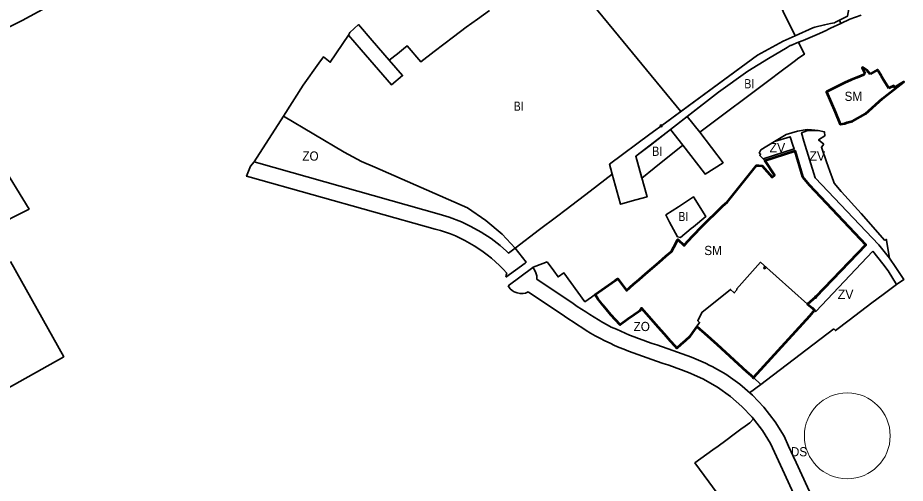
# Model space of a CAD drawing. Extents: x -650276 to -642489, y -1074311 to -1066720.
# Drawn here: x -648741 to -647583, y -1071705 to -1071099 of the extents above; entities that cross this region are included whole.
import ezdxf

# ---------------------------------------------------------------- set-up
doc = ezdxf.new("R2010")
doc.units = 0
doc.header["$LTSCALE"] = 4.8
doc.header["$PDMODE"] = 32
doc.header["$PDSIZE"] = 2.4
for name, color, linetype, lineweight in [('1', 7, 'Continuous', 35), ('15', 7, 'Continuous', 35), ('18', 7, 'Continuous', 35), ('2', 7, 'Continuous', 35), ('24', 7, 'Continuous', 35), ('40', 7, 'Continuous', 35), ('42', 7, 'Continuous', 35), ('54', 7, 'Continuous', 35), ('60', 7, 'Continuous', 53), ('7', 7, 'Continuous', 35)]:
    doc.layers.add(name, color=color, linetype=linetype, lineweight=lineweight)
doc.layers.add('62', color=7, linetype='Continuous')

msp = doc.modelspace()

# ---------------------------------------------------------------- linework, layer by layer
at = {"layer": '1'}
msp.add_lwpolyline([(-648001.922, -1071067.83), (-647977.41, -1071049.74), (-647930.7, -1071017.18), (-647911.838, -1071002.919), (-647864.03, -1070969.3), (-647864.03, -1070969.3), (-647818.33, -1070942.91), (-647810.243, -1070939.825), (-647759.52, -1071055.67), (-647757.19, -1071059.66), (-647742.64, -1071090.72), (-647726.74, -1071122.48), (-647742.35, -1071129.43), (-647775.982, -1071148.001), (-647775.982, -1071148.001), (-647875.939, -1071221.104)], close=True, dxfattribs=at)
at = {"layer": '15'}
for p, q in [((-647873.25, -1071265.17), (-647845.18, -1071301.54)), ((-647708.429, -1071316.821), (-647717.363, -1071306.29))]:
    msp.add_line(p, q, dxfattribs=at)
for points in [[(-647676.96, -1071039.014), (-647676.9, -1071039.03), (-647676.45, -1071039.22), (-647656.443, -1071085.369), (-647658.55, -1071097.02), (-647669.02, -1071102.33), (-647667.35, -1071106.38), (-647655.47, -1071100.98), (-647640.727, -1071095.819)], [(-647845.18, -1071301.54), (-647844.296, -1071302.757), (-647820.698, -1071287.83), (-647850.956, -1071248.208), (-647867.586, -1071227.694), (-647889.22, -1071244.48), (-647873.25, -1071265.17)]]:
    msp.add_lwpolyline(points, dxfattribs=at)
for points in [[(-648238.84, -1071174.33), (-648256.04, -1071154.5), (-648278.39, -1071128.74), (-648296.34, -1071108.04), (-648307.33, -1071118.47), (-648309.41, -1071121.655), (-648292.587, -1071141.054), (-648270.236, -1071166.815), (-648253.126, -1071186.542)], [(-647826.56, -1071195.86), (-647788.66, -1071168.8), (-647761.366, -1071152.304), (-647737.027, -1071137.593), (-647733.38, -1071135.37), (-647732.58, -1071135.04), (-647722.51, -1071130.93), (-647716.51, -1071128.48), (-647695.08, -1071119.72), (-647685.55, -1071115.14), (-647684.15, -1071114.47), (-647680.64, -1071112.77), (-647667.35, -1071106.38), (-647669.02, -1071102.33), (-647674.17, -1071104.97), (-647675.64, -1071105.71), (-647680.82, -1071106.54), (-647688.45, -1071108.38), (-647701.04, -1071111.41), (-647703.96, -1071112.11), (-647726.74, -1071122.48), (-647742.35, -1071129.43), (-647775.982, -1071148.001), (-647895.959, -1071235.746), (-647916.161, -1071250.628), (-647916.208, -1071250.662), (-647968.896, -1071289.779), (-647965.26, -1071302.86), (-647954.38, -1071342), (-647934.51, -1071336.37), (-647919.88, -1071332.23), (-647924.53, -1071315.55), (-647934.6, -1071279.45), (-647915.6, -1071264.95), (-647889.22, -1071244.48)], [(-647625.428, -1071403.267), (-647612.269, -1071419.742), (-647605.292, -1071428.816), (-647594.43, -1071446.543), (-647585.273, -1071440.044), (-647595.335, -1071424.564), (-647603.9, -1071412.1), (-647617.49, -1071394.901), (-647700.816, -1071307.512), (-647715.355, -1071259.885), (-647718.342, -1071248.972), (-647711.447, -1071246.332), (-647696.81, -1071245.79), (-647705.59, -1071245.08), (-647710.94, -1071244.65), (-647723.57, -1071246.66), (-647738.56, -1071251.13), (-647753.647, -1071260.178), (-647733.15, -1071254.081), (-647729.795, -1071265.066), (-647728.006, -1071269.975), (-647768.445, -1071282.6), (-647772.97, -1071278.43), (-647772.07, -1071279.33), (-647766.35, -1071285.11), (-647727.368, -1071272.362), (-647717.363, -1071306.29), (-647708.429, -1071316.821), (-647634.524, -1071394.901), (-647700.078, -1071462.96), (-647710.546, -1071472.023), (-647699.767, -1071481.617)]]:
    msp.add_lwpolyline(points, close=True, dxfattribs=at)
for p in [(-647766.557, -1071424.793), (-647700.078, -1071462.96)]:
    msp.add_point(p, dxfattribs=at)
at = {"layer": '18'}
for points in [[(-647629.09, -1071172.4), (-647632.93, -1071167.71), (-647638.46, -1071163.89), (-647639.32, -1071164.22), (-647635.93, -1071171.22)], [(-647612.695, -1071177.542), (-647613.91, -1071175.57), (-647614.732, -1071174.222), (-647618.446, -1071168.166), (-647618.469, -1071168.129), (-647618.77, -1071167.64), (-647619.264, -1071166.832), (-647619.34, -1071166.709), (-647628.39, -1071172.05), (-647629.09, -1071172.4)], [(-647635.93, -1071171.22), (-647637.87, -1071173.29), (-647646.09, -1071176.68), (-647653.85, -1071179.87), (-647662.634, -1071183.968)], [(-647604.576, -1071190.781), (-647604.888, -1071190.272), (-647612.695, -1071177.542)], [(-647662.634, -1071183.968), (-647686.01, -1071195.35), (-647686.01, -1071195.35)], [(-647674.6, -1071221.71), (-647668.226, -1071237.571), (-647667.77, -1071237.5), (-647661.99, -1071236.62), (-647658.78, -1071235.63), (-647651.93, -1071233.57), (-647635.17, -1071224.18), (-647613.09, -1071204.33), (-647607.02, -1071199.34), (-647584.92, -1071182.54), (-647597.164, -1071189.857), (-647598.215, -1071187.608), (-647604.576, -1071190.781)], [(-647686.01, -1071195.35), (-647686.01, -1071195.35), (-647674.6, -1071221.71)]]:
    msp.add_lwpolyline(points, dxfattribs=at)
msp.add_lwpolyline([(-647974.66, -1071450.62), (-647977.28, -1071452.43), (-647979.88, -1071454.22), (-647982.46, -1071456), (-647985.06, -1071457.79), (-647987.8, -1071459.68), (-647984.07, -1071465.1), (-647977.13, -1071474.05), (-647972.76, -1071479), (-647967.13, -1071486.01), (-647957.07, -1071497.13), (-647955.14, -1071499.23), (-647950.56, -1071495.85), (-647944.81, -1071491.78), (-647939.31, -1071487.88), (-647933.88, -1071484.04), (-647931.17, -1071482.12), (-647929.26, -1071480.77), (-647927.2, -1071477.54), (-647919.22, -1071486.5), (-647881.16, -1071529.25), (-647876.27, -1071524.96), (-647864.69, -1071514.65), (-647851.45, -1071495.96), (-647853.77, -1071493.78), (-647848.4, -1071482.78), (-647810.97, -1071452.92), (-647806.15, -1071457.48), (-647802.53, -1071453.19), (-647803.1, -1071452.66), (-647771.82, -1071417.42), (-647710.546, -1071472.023), (-647700.078, -1071462.96), (-647634.524, -1071394.901), (-647708.429, -1071316.821), (-647717.363, -1071306.29), (-647727.368, -1071272.362), (-647766.35, -1071285.11), (-647753.89, -1071303.94), (-647756.67, -1071306.77), (-647769.85, -1071291.91), (-647774.14, -1071291.34), (-647777.4, -1071291.32), (-647815.95, -1071339.71), (-647820.93, -1071344.25), (-647849.86, -1071372.18), (-647867.45, -1071390.95), (-647871.68, -1071395.59), (-647879.76, -1071387.96), (-647885.05, -1071397.88), (-647888.11, -1071403.61), (-647895.29, -1071409.81), (-647904.3, -1071417.58), (-647911.04, -1071423.39), (-647913.31, -1071425.35), (-647921.96, -1071432.81), (-647946.78, -1071454.23), (-647957.906, -1071439.06)], close=True, dxfattribs=at)
at = {"layer": '2'}
for points in [[(-648125.53, -1071089.51), (-648141.12, -1071100.71), (-648155.77, -1071111.23), (-648172.48, -1071123.95), (-648197.57, -1071143.03), (-648215.08, -1071156.35), (-648232.8, -1071135.6), (-648237.46, -1071139.38), (-648245.49, -1071145.91), (-648256.04, -1071154.5), (-648238.84, -1071174.33), (-648253.126, -1071186.542), (-648292.587, -1071141.054), (-648309.41, -1071121.655), (-648333.002, -1071157.07), (-648341.943, -1071150.071), (-648347.949, -1071158.385), (-648368.48, -1071186.81), (-648394.104, -1071227.17), (-648315.127, -1071274.052), (-648292.406, -1071286.112), (-648274.918, -1071293.751), (-648154.21, -1071346.477), (-648130, -1071363), (-648109, -1071381), (-648091.92, -1071399.07), (-648060.01, -1071374.69), (-648038.18, -1071358.51), (-648025.39, -1071348.76), (-647994.31, -1071325.03), (-647965.26, -1071302.86), (-647966.226, -1071299.385), (-647968.896, -1071289.779), (-647916.208, -1071250.662), (-647895.959, -1071235.746), (-647875.939, -1071221.104), (-648001.922, -1071067.83)], [(-647889.22, -1071244.48), (-647915.6, -1071264.95), (-647934.6, -1071279.45), (-647926.689, -1071307.809), (-647910.73, -1071295.08)], [(-647910.73, -1071295.08), (-647907.92, -1071292.84), (-647888.77, -1071277.56), (-647873.25, -1071265.17), (-647889.22, -1071244.48)], [(-648764.17, -1071286.65), (-648725.85, -1071348.28), (-648774.371, -1071372.773)], [(-648749.854, -1071416.727), (-648680.709, -1071540.691), (-648835.095, -1071627.059)]]:
    msp.add_lwpolyline(points, dxfattribs=at)
for points in [[(-647756.03, -1071176.76), (-647750.34, -1071172.5), (-647726.56, -1071154.68), (-647723.79, -1071152.61), (-647720.85, -1071150.41), (-647714.71, -1071146.51), (-647719.73, -1071136.48), (-647722.51, -1071130.93), (-647732.58, -1071135.04), (-647733.38, -1071135.37), (-647737.027, -1071137.593), (-647761.366, -1071152.304), (-647788.66, -1071168.8), (-647826.56, -1071195.86), (-647867.586, -1071227.694), (-647850.956, -1071248.208)], [(-647926.69, -1071307.81), (-647934.6, -1071279.45), (-647889.22, -1071244.48), (-647873.25, -1071265.17), (-647888.77, -1071277.56), (-647907.92, -1071292.84), (-647910.73, -1071295.08)], [(-647879.09, -1071345.3), (-647895.37, -1071355.96), (-647890.7, -1071365.52), (-647880.14, -1071384.32), (-647876.34, -1071385.2), (-647862.25, -1071373.55), (-647859.44, -1071371.23), (-647843.23, -1071357.82), (-647859.31, -1071332.34)]]:
    msp.add_lwpolyline(points, close=True, dxfattribs=at)
msp.add_point((-647901.523, -1071239.822), dxfattribs=at)
at = {"layer": '24'}
for points in [[(-648103.894, -1071436.836), (-648079.108, -1071418.564), (-648077.53, -1071417.4), (-648091.92, -1071399.07), (-648100.438, -1071405.517), (-648103.268, -1071402.88), (-648111.646, -1071395.618), (-648123.313, -1071386.696), (-648136.263, -1071378.194), (-648149.571, -1071370.788), (-648162.084, -1071364.918), (-648178.158, -1071358.781), (-648191.25, -1071354.858), (-648426.18, -1071288.32), (-648432.093, -1071286.645), (-648437.16, -1071292.53), (-648442.191, -1071305.453), (-648437.454, -1071306.778), (-648196.236, -1071374.226)], [(-648063.593, -1071439.723), (-648063.862, -1071435.078), (-648064.838, -1071431.28), (-648066.623, -1071427.592), (-648069.022, -1071424.443), (-648101.203, -1071448.31)], [(-647834.953, -1071553.406), (-647837.929, -1071551.872), (-647843.891, -1071549), (-647849.898, -1071546.282), (-647855.937, -1071543.707), (-647861.998, -1071541.254), (-647868.073, -1071538.911), (-647874.155, -1071536.658), (-647880.233, -1071534.48), (-647886.305, -1071532.36), (-647892.363, -1071530.282), (-647901.28, -1071527.249), (-647907.294, -1071525.204), (-647913.282, -1071523.152), (-647919.238, -1071521.081), (-647925.157, -1071518.976), (-647931.035, -1071516.824), (-647936.866, -1071514.613), (-647942.644, -1071512.329), (-647948.363, -1071509.96), (-647954.016, -1071507.496), (-647959.792, -1071504.833), (-647966.547, -1071501.883), (-647972.035, -1071499.009), (-647977.67, -1071495.885), (-647983.266, -1071492.628), (-647988.829, -1071489.259), (-647994.366, -1071485.79), (-647999.887, -1071482.241), (-648005.399, -1071478.627), (-648010.917, -1071474.963), (-648016.446, -1071471.268), (-648063.593, -1071439.723)], [(-648101.203, -1071448.31), (-648098.259, -1071452.196), (-648096.014, -1071454.192), (-648093.059, -1071456.066), (-648089.539, -1071457.489), (-648085.585, -1071458.248), (-648081.642, -1071458.215), (-648078.539, -1071457.636), (-648074.86, -1071456.248)], [(-648074.86, -1071456.248), (-648027.562, -1071487.894), (-648022.005, -1071491.607), (-648016.415, -1071495.321), (-648010.777, -1071499.017), (-648005.082, -1071502.678), (-647999.319, -1071506.287), (-647993.478, -1071509.826), (-647987.55, -1071513.275), (-647981.525, -1071516.615), (-647975.201, -1071519.929), (-647967.982, -1071523.081), (-647962.2, -1071525.746), (-647956.187, -1071528.368), (-647950.146, -1071530.869), (-647944.088, -1071533.263), (-647938.019, -1071535.566), (-647931.945, -1071537.788), (-647925.874, -1071539.949), (-647919.808, -1071542.058), (-647913.756, -1071544.132), (-647907.72, -1071546.185), (-647898.827, -1071549.208), (-647892.847, -1071551.26), (-647886.903, -1071553.336), (-647881.001, -1071555.45), (-647875.147, -1071557.619), (-647869.348, -1071559.856), (-647863.611, -1071562.177), (-647857.944, -1071564.594), (-647847.103, -1071569.497)], [(-647725.629, -1071678.373), (-647735.352, -1071657.117), (-647741.34, -1071644.028), (-647753.065, -1071625.201), (-647767.784, -1071606.225), (-647782.408, -1071590.847), (-647798.911, -1071576.526), (-647817.375, -1071563.458), (-647834.953, -1071553.406)], [(-647847.103, -1071569.497), (-647828.141, -1071580.34), (-647811.272, -1071592.28), (-647796.24, -1071605.324), (-647782.97, -1071619.278)], [(-647782.97, -1071619.278), (-647769.498, -1071636.647), (-647758.994, -1071653.513), (-647743.48, -1071687.426), (-647611.514, -1071974.086)], [(-647570.747, -1071972.644), (-647538.922, -1071950.099), (-647551.962, -1071958.049), (-647573.283, -1071969.627), (-647575.415, -1071967.709), (-647577.881, -1071965.979), (-647581.036, -1071964.346), (-647584.363, -1071963.196), (-647588.064, -1071962.51), (-647591.518, -1071962.387), (-647594.731, -1071962.714), (-647725.614, -1071678.405), (-647726.774, -1071675.885), (-647725.629, -1071678.373)]]:
    msp.add_lwpolyline(points, dxfattribs=at)
for centre, radius, start, end in [((-648244.965, -1071557.871), 190, 41.59858, 75.13936), ((-648083.781, -1071438.172), 20.157, 161.35794, 176.20098)]:
    msp.add_arc(centre, radius, start, end, dxfattribs=at)
at = {"layer": '40'}
msp.add_line((-647617.49, -1071394.901), (-647603.9, -1071412.1), dxfattribs=at)
for points in [[(-647696.81, -1071245.79), (-647711.447, -1071246.332), (-647718.342, -1071248.972), (-647715.355, -1071259.885), (-647700.816, -1071307.512), (-647617.49, -1071394.901)], [(-647689.61, -1071263.51), (-647696.35, -1071258.14), (-647688.17, -1071253.06), (-647688.46, -1071247.65), (-647696.81, -1071245.79)], [(-647728.006, -1071269.975), (-647729.795, -1071265.066), (-647733.15, -1071254.081), (-647753.647, -1071260.178), (-647771.76, -1071271.04)], [(-647771.76, -1071271.04), (-647773.6, -1071275.43), (-647771.59, -1071277.36), (-647772.97, -1071278.43), (-647768.445, -1071282.6), (-647728.006, -1071269.975)], [(-647666.78, -1071325.52), (-647675.85, -1071314.62), (-647677, -1071312.01), (-647681.53, -1071299.02), (-647685.74, -1071286.93), (-647692.45, -1071267.67), (-647689.61, -1071263.51)], [(-647609.85, -1071389.21), (-647640.92, -1071354.21), (-647666.21, -1071325.89), (-647666.629, -1071325.351), (-647666.78, -1071325.52)], [(-647603.9, -1071412.1), (-647606.39, -1071397.21), (-647607.77, -1071388.91), (-647608.31, -1071387.63), (-647609.85, -1071389.21)], [(-647625.428, -1071403.267), (-647699.767, -1071481.617), (-647701.415, -1071480.15), (-647708.18, -1071487.57), (-647776.13, -1071562.1)], [(-647676.51, -1071504.34), (-647674.28, -1071506.59), (-647656.27, -1071493.04), (-647626.7, -1071470.46), (-647611.82, -1071459.38), (-647594.43, -1071446.543), (-647605.292, -1071428.816), (-647612.269, -1071419.742), (-647625.428, -1071403.267)], [(-647776.13, -1071562.1), (-647781.31, -1071567.79), (-647771.717, -1071576.551), (-647764.23, -1071571.01), (-647676.51, -1071504.34)]]:
    msp.add_lwpolyline(points, dxfattribs=at)
at = {"layer": '42'}
for p, q in [((-648394.104, -1071227.17), (-648432.093, -1071286.645)), ((-647984.07, -1071465.1), (-647987.8, -1071459.68)), ((-647849.898, -1071546.282), (-647843.891, -1071549))]:
    msp.add_line(p, q, dxfattribs=at)
for points in [[(-648292.406, -1071286.112), (-648315.127, -1071274.052), (-648394.104, -1071227.17), (-648432.093, -1071286.645)], [(-648432.093, -1071286.645), (-648426.18, -1071288.32), (-648191.25, -1071354.858)], [(-648091.92, -1071399.07), (-648109, -1071381), (-648130, -1071363), (-648154.21, -1071346.477), (-648274.918, -1071293.751), (-648292.406, -1071286.112)], [(-648191.25, -1071354.858), (-648178.158, -1071358.781), (-648162.084, -1071364.918), (-648149.571, -1071370.788), (-648136.263, -1071378.194), (-648123.313, -1071386.696), (-648111.646, -1071395.618), (-648103.268, -1071402.88), (-648100.438, -1071405.517), (-648091.92, -1071399.07)], [(-648050.25, -1071417.19), (-648055.717, -1071419.253), (-648068.56, -1071424.1), (-648069.022, -1071424.443)], [(-647987.8, -1071459.68), (-647988.713, -1071460.33), (-647992.408, -1071462.858), (-648000.91, -1071469.01), (-648028.31, -1071431.32), (-648035.87, -1071436.62), (-648041.726, -1071428.707), (-648050.25, -1071417.19)], [(-648069.022, -1071424.443), (-648066.623, -1071427.592), (-648064.838, -1071431.28), (-648063.862, -1071435.078), (-648063.593, -1071439.723), (-648016.446, -1071471.268), (-648010.917, -1071474.963), (-648005.399, -1071478.627), (-647999.887, -1071482.241), (-647994.366, -1071485.79)], [(-647944.81, -1071491.78), (-647950.56, -1071495.85), (-647955.14, -1071499.23), (-647957.07, -1071497.13), (-647967.13, -1071486.01), (-647972.76, -1071479), (-647977.13, -1071474.05)], [(-647927.2, -1071477.54), (-647927.2, -1071477.54), (-647929.26, -1071480.77), (-647931.17, -1071482.12), (-647933.88, -1071484.04), (-647939.31, -1071487.88), (-647944.81, -1071491.78)], [(-647855.23, -1071501.297), (-647864.69, -1071514.65), (-647876.27, -1071524.96), (-647881.16, -1071529.25), (-647919.22, -1071486.5), (-647927.2, -1071477.54)], [(-647994.366, -1071485.79), (-647988.829, -1071489.259), (-647983.266, -1071492.628)], [(-647983.266, -1071492.628), (-647977.67, -1071495.885), (-647972.035, -1071499.009), (-647966.547, -1071501.883), (-647959.792, -1071504.833)], [(-647828.024, -1071525.256), (-647844.4, -1071510.2), (-647850.55, -1071505.14), (-647855.23, -1071501.297)], [(-647959.792, -1071504.833), (-647954.016, -1071507.496), (-647948.363, -1071509.96)], [(-647948.363, -1071509.96), (-647942.644, -1071512.329), (-647936.866, -1071514.613)], [(-647936.866, -1071514.613), (-647931.035, -1071516.824), (-647925.157, -1071518.976), (-647919.238, -1071521.081), (-647913.282, -1071523.152)], [(-647781.31, -1071567.79), (-647789.73, -1071560.1), (-647844.4, -1071510.2), (-647828.024, -1071525.256)], [(-647913.282, -1071523.152), (-647907.294, -1071525.204), (-647901.28, -1071527.249)], [(-647901.28, -1071527.249), (-647892.363, -1071530.282), (-647886.305, -1071532.36), (-647880.233, -1071534.48), (-647874.155, -1071536.658), (-647868.073, -1071538.911), (-647861.998, -1071541.254), (-647855.937, -1071543.707), (-647849.898, -1071546.282)], [(-647843.891, -1071549), (-647837.929, -1071551.872), (-647834.953, -1071553.406)], [(-647834.953, -1071553.406), (-647817.375, -1071563.458), (-647798.911, -1071576.526), (-647786.379, -1071587.401), (-647771.717, -1071576.551), (-647781.31, -1071567.79)], [(-647727.85, -1071854.86), (-647857.52, -1071678.92), (-647834.345, -1071661.969), (-647827.42, -1071656.89), (-647817.33, -1071649.51), (-647806.35, -1071641.47), (-647795.76, -1071633.72), (-647794.98, -1071633.15), (-647786.1, -1071626.65), (-647781.134, -1071621.645), (-647769.498, -1071636.647), (-647758.889, -1071653.742), (-647743.48, -1071687.426), (-647611.514, -1071974.086)]]:
    msp.add_lwpolyline(points, dxfattribs=at)
msp.add_point((-647781.31, -1071567.79), dxfattribs=at)
at = {"layer": '54', "lineweight": 13}
msp.add_circle((-647658.811, -1071643.674), 55.982, dxfattribs=at)
at = {"layer": '60'}
for points in [[(-647629.09, -1071172.4), (-647632.93, -1071167.71), (-647638.46, -1071163.89), (-647639.32, -1071164.22), (-647635.93, -1071171.22)], [(-647612.695, -1071177.542), (-647613.91, -1071175.57), (-647614.732, -1071174.222), (-647618.446, -1071168.166), (-647618.469, -1071168.129), (-647618.77, -1071167.64), (-647619.264, -1071166.832), (-647619.34, -1071166.709), (-647628.39, -1071172.05), (-647629.09, -1071172.4)], [(-647635.93, -1071171.22), (-647637.87, -1071173.29), (-647646.09, -1071176.68), (-647653.85, -1071179.87), (-647662.634, -1071183.968)], [(-647604.576, -1071190.781), (-647604.888, -1071190.272), (-647612.695, -1071177.542)], [(-647662.634, -1071183.968), (-647686.01, -1071195.35), (-647686.01, -1071195.35)], [(-647674.6, -1071221.71), (-647668.226, -1071237.571), (-647667.77, -1071237.5), (-647661.99, -1071236.62), (-647658.78, -1071235.63), (-647651.93, -1071233.57), (-647635.17, -1071224.18), (-647613.09, -1071204.33), (-647607.02, -1071199.34), (-647584.92, -1071182.54), (-647597.164, -1071189.857), (-647598.215, -1071187.608), (-647604.576, -1071190.781)], [(-647686.01, -1071195.35), (-647686.01, -1071195.35), (-647674.6, -1071221.71)]]:
    msp.add_lwpolyline(points, dxfattribs=at)
msp.add_lwpolyline([(-647777.4, -1071291.32), (-647777.4, -1071291.32), (-647774.14, -1071291.34), (-647769.85, -1071291.91), (-647756.67, -1071306.77), (-647753.89, -1071303.94), (-647766.35, -1071285.11), (-647727.368, -1071272.362), (-647717.363, -1071306.29), (-647708.429, -1071316.821), (-647634.524, -1071394.901), (-647700.078, -1071462.96), (-647710.546, -1071472.023), (-647704.78, -1071477.1), (-647701.415, -1071480.15), (-647708.18, -1071487.57), (-647767.575, -1071553.083), (-647781.31, -1071567.79), (-647789.73, -1071560.1), (-647828.024, -1071525.256), (-647844.4, -1071510.2), (-647850.55, -1071505.14), (-647855.23, -1071501.297), (-647860.576, -1071508.843), (-647864.69, -1071514.65), (-647869.922, -1071519.269), (-647876.29, -1071524.89), (-647881.16, -1071529.25), (-647883.31, -1071526.83), (-647889.29, -1071520.11), (-647897.27, -1071511.15), (-647905.25, -1071502.19), (-647917.23, -1071488.75), (-647927.2, -1071477.54), (-647929.26, -1071480.77), (-647931.17, -1071482.12), (-647936.59, -1071485.96), (-647944.81, -1071491.78), (-647955.14, -1071499.23), (-647967.13, -1071486.01), (-647972.76, -1071479), (-647977.13, -1071474.05), (-647984.07, -1071465.1), (-647987.8, -1071459.68), (-647961.4, -1071441.47), (-647957.906, -1071439.06), (-647946.78, -1071454.23), (-647937.43, -1071446.16), (-647930.38, -1071440.08), (-647921.96, -1071432.81), (-647913.31, -1071425.35), (-647904.3, -1071417.58), (-647895.29, -1071409.81), (-647888.11, -1071403.61), (-647885.05, -1071397.88), (-647879.76, -1071387.96), (-647871.68, -1071395.59), (-647867.45, -1071390.95), (-647849.86, -1071372.18), (-647820.93, -1071344.25), (-647815.474, -1071339.22)], close=True, dxfattribs=at)
at = {"layer": '7'}
msp.add_lwpolyline([(-648866.341, -1071000.881), (-648828.353, -1071043.265), (-648785.386, -1071084.634), (-648758.423, -1071107.756), (-648752.967, -1071111.861), (-648734.849, -1071102.599), (-648651.375, -1071057.109), (-648627.39, -1071042.65), (-648655.76, -1070997.5), (-648634.07, -1070983.17), (-648571.14, -1070944.67), (-648540.7, -1070928.6), (-648479.18, -1070891.26), (-648386.587, -1070833.807), (-648427.25, -1070767.95), (-648511.09, -1070814.7), (-648721.54, -1070930.88), (-648740.25, -1070941.21), (-648774.23, -1070956.42)], close=True, dxfattribs=at)

# ---------------------------------------------------------------- texts
at = {"layer": '62'}
for s, width, p in [('BI', 0.85, (-647793.1, -1071190.942)), ('SM', 0.95, (-647662.328, -1071207.374)), ('BI', 0.85, (-648093.764, -1071220.263)), ('BI', 0.85, (-647913.1, -1071278.942)), ('ZO', 0.95, (-648369.423, -1071285.188)), ('BI', 0.85, (-647879.1, -1071363.942)), ('SM', 0.95, (-647845.307, -1071408.18)), ('ZO', 0.95, (-647937.423, -1071507.188)), ('DS', 0.95, (-647732.378, -1071670.379))]:
    msp.add_text(s, height=12, dxfattribs=dict(at, width=width)).set_placement(p)
for p in [(-647760.241, -1071274.214), (-647708.241, -1071285.214), (-647671.241, -1071465.214)]:
    msp.add_text('ZV', height=12, dxfattribs=at).set_placement(p)

doc.saveas('drawing.dxf')
